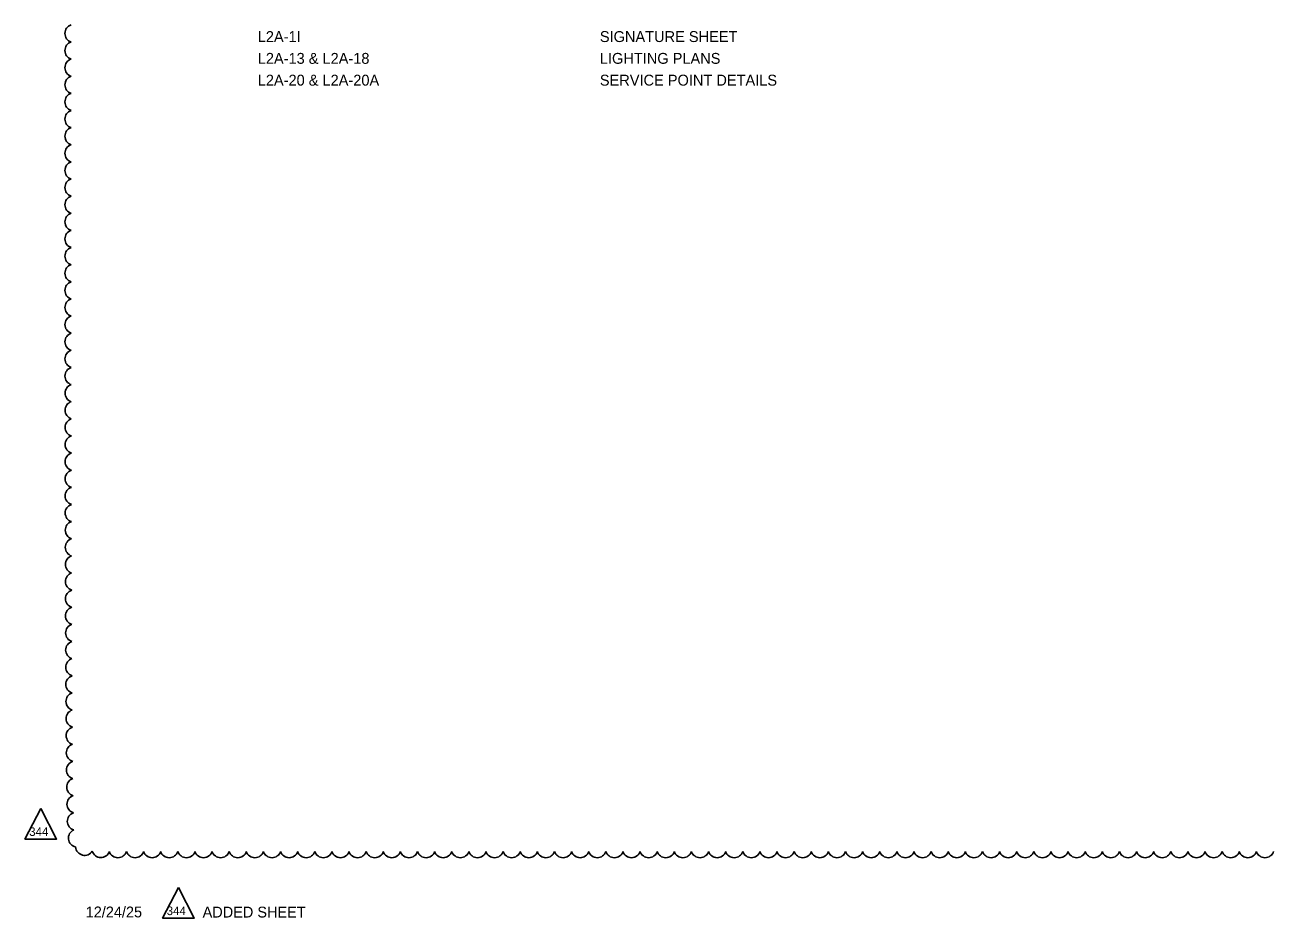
# Model space of a CAD drawing. Extents: x -811 to 10319, y -2309 to 9962.
# Drawn here: x -811.27 to -803.29, y -2308.89 to -2303.15 of the extents above; entities that cross this region are included whole.
import ezdxf

# ---------------------------------------------------------------- set-up
doc = ezdxf.new("R2010")
doc.units = 0
doc.layers.add('ScratchEle_dp', color=7, linetype='Continuous')
doc.layers.add('TextMisc', color=7, linetype='Continuous')

msp = doc.modelspace()

# ---------------------------------------------------------------- linework, layer by layer
at = {"layer": 'ScratchEle_dp'}
for points in [[(-811.1719, -2308.1812), (-811.2741, -2308.3778), (-811.0698, -2308.3778)], [(-810.2869, -2308.6886), (-810.389, -2308.8853), (-810.1848, -2308.8853)]]:
    msp.add_lwpolyline(points, close=True, dxfattribs=at)
for centre, radius, start, end in [((-810.959, -2303.2017), 0.0577, 107.5, 252.5), ((-810.959, -2303.3118), 0.0577, 107.5, 252.5), ((-810.959, -2303.4218), 0.0577, 107.5, 252.5), ((-810.959, -2303.5318), 0.0577, 107.5, 252.5), ((-810.959, -2303.6419), 0.0577, 107.5, 252.5), ((-810.959, -2303.7519), 0.0577, 107.5, 252.5), ((-810.959, -2303.862), 0.0577, 107.5, 252.5), ((-810.959, -2303.972), 0.0577, 107.5, 252.5), ((-810.959, -2304.0821), 0.0577, 107.50009, 252.50009), ((-810.959, -2304.1921), 0.0577, 107.50287, 252.50287), ((-810.959, -2304.3021), 0.0577, 107.50707, 252.50707), ((-810.9589, -2304.4122), 0.0577, 107.51144, 252.51144), ((-810.9589, -2304.5222), 0.0577, 107.51599, 252.51599), ((-810.9589, -2304.6323), 0.0577, 107.52073, 252.52073), ((-810.9588, -2304.7423), 0.0577, 107.52569, 252.52569), ((-810.9588, -2304.8524), 0.0577, 107.53088, 252.53088), ((-810.9587, -2304.9624), 0.0577, 107.53631, 252.53631), ((-810.9586, -2305.0724), 0.0577, 107.54201, 252.54201), ((-810.9585, -2305.1825), 0.0577, 107.548, 252.548), ((-810.9584, -2305.2925), 0.0577, 107.5543, 252.5543), ((-810.9583, -2305.4026), 0.0577, 107.56094, 252.56094), ((-810.9582, -2305.5126), 0.0577, 107.56795, 252.56795), ((-810.9581, -2305.6227), 0.0577, 107.57537, 252.57537), ((-810.9579, -2305.7327), 0.0577, 107.58325, 252.58325), ((-810.9578, -2305.8427), 0.0577, 107.59162, 252.59162), ((-810.9576, -2305.9528), 0.0577, 107.60055, 252.60055), ((-810.9574, -2306.0628), 0.0577, 107.61009, 252.61009), ((-810.9571, -2306.1729), 0.0577, 107.62033, 252.62033), ((-810.9569, -2306.2829), 0.0577, 107.63135, 252.63135), ((-810.9566, -2306.3929), 0.0577, 107.64325, 252.64325), ((-810.9564, -2306.503), 0.0577, 107.65616, 252.65616), ((-810.956, -2306.613), 0.0577, 107.67024, 252.67024), ((-810.9557, -2306.7231), 0.0577, 107.68566, 252.68566), ((-810.9553, -2306.8331), 0.0577, 107.70266, 252.70266), ((-810.9549, -2306.9431), 0.0577, 107.72152, 252.72152), ((-810.9545, -2307.0532), 0.0577, 107.74262, 252.74262), ((-810.954, -2307.1632), 0.0577, 107.76643, 252.76643), ((-810.9534, -2307.2732), 0.0577, 107.79359, 252.79359), ((-810.9529, -2307.3833), 0.0577, 107.82496, 252.82496), ((-810.9522, -2307.4933), 0.0577, 107.86178, 252.86178), ((-810.9515, -2307.6033), 0.0577, 107.9058, 252.9058), ((-810.9506, -2307.7134), 0.0577, 107.95976, 252.95976), ((-810.9497, -2307.8234), 0.0577, 108.02807, 253.02807), ((-810.9486, -2307.9334), 0.0577, 108.11849, 253.11849), ((-810.9473, -2308.0434), 0.0577, 108.24639, 253.24639), ((-810.9456, -2308.1533), 0.0577, 108.44819, 253.44819), ((-810.9434, -2308.2632), 0.0577, 108.8456, 253.8456), ((-810.9363, -2308.3715), 0.0577, 113.71802, 258.71802), ((-810.89, -2308.4245), 0.0576, 183.636, 328.636), ((-810.7854, -2308.4383), 0.0577, 196.27453, 341.27453), ((-810.6758, -2308.4395), 0.0577, 197.5, 342.5), ((-810.5657, -2308.4395), 0.0577, 197.5, 342.5), ((-810.4557, -2308.4395), 0.0577, 197.5, 342.5), ((-810.3457, -2308.4395), 0.0577, 197.5, 342.5), ((-810.2356, -2308.4395), 0.0577, 197.5, 342.5), ((-810.1256, -2308.4395), 0.0577, 197.5, 342.5), ((-810.0155, -2308.4395), 0.0577, 197.5, 342.5), ((-809.9055, -2308.4395), 0.0577, 197.5, 342.5), ((-809.7954, -2308.4395), 0.0577, 197.5, 342.5), ((-809.6854, -2308.4395), 0.0577, 197.5, 342.5), ((-809.5753, -2308.4395), 0.0577, 197.5, 342.5), ((-809.4653, -2308.4395), 0.0577, 197.5, 342.5), ((-809.3553, -2308.4395), 0.0577, 197.5, 342.5), ((-809.2452, -2308.4395), 0.0577, 197.5, 342.5), ((-809.1352, -2308.4395), 0.0577, 197.5, 342.5), ((-809.0251, -2308.4395), 0.0577, 197.5, 342.5), ((-808.9151, -2308.4395), 0.0577, 197.5, 342.5), ((-808.805, -2308.4395), 0.0577, 197.5, 342.5), ((-808.695, -2308.4395), 0.0577, 197.5, 342.5), ((-808.585, -2308.4395), 0.0577, 197.5, 342.5), ((-808.4749, -2308.4395), 0.0577, 197.5, 342.5), ((-808.3649, -2308.4395), 0.0577, 197.5, 342.5), ((-808.2548, -2308.4395), 0.0577, 197.5, 342.5), ((-808.1448, -2308.4395), 0.0577, 197.5, 342.5), ((-808.0347, -2308.4395), 0.0577, 197.5, 342.5), ((-807.9247, -2308.4395), 0.0577, 197.5, 342.5), ((-807.8146, -2308.4395), 0.0577, 197.5, 342.5), ((-807.7046, -2308.4395), 0.0577, 197.5, 342.5), ((-807.5946, -2308.4395), 0.0577, 197.5, 342.5), ((-807.4845, -2308.4395), 0.0577, 197.5, 342.5), ((-807.3745, -2308.4395), 0.0577, 197.5, 342.5), ((-807.2644, -2308.4395), 0.0577, 197.5, 342.5), ((-807.1544, -2308.4395), 0.0577, 197.5, 342.5), ((-807.0443, -2308.4395), 0.0577, 197.5, 342.5), ((-806.9343, -2308.4395), 0.0577, 197.5, 342.5), ((-806.8242, -2308.4395), 0.0577, 197.5, 342.5), ((-806.7142, -2308.4395), 0.0577, 197.5, 342.5), ((-806.6042, -2308.4395), 0.0577, 197.5, 342.5), ((-806.4941, -2308.4395), 0.0577, 197.5, 342.5), ((-806.3841, -2308.4395), 0.0577, 197.5, 342.5), ((-806.274, -2308.4395), 0.0577, 197.5, 342.5), ((-806.164, -2308.4395), 0.0577, 197.5, 342.5), ((-806.0539, -2308.4395), 0.0577, 197.5, 342.5), ((-805.9439, -2308.4395), 0.0577, 197.5, 342.5), ((-805.8339, -2308.4395), 0.0577, 197.5, 342.5), ((-805.7238, -2308.4395), 0.0577, 197.5, 342.5), ((-805.6138, -2308.4395), 0.0577, 197.5, 342.5), ((-805.5037, -2308.4395), 0.0577, 197.5, 342.5), ((-805.3937, -2308.4395), 0.0577, 197.5, 342.5), ((-805.2836, -2308.4395), 0.0577, 197.5, 342.5), ((-805.1736, -2308.4395), 0.0577, 197.5, 342.5), ((-805.0635, -2308.4395), 0.0577, 197.5, 342.5), ((-804.9535, -2308.4395), 0.0577, 197.5, 342.5), ((-804.8435, -2308.4395), 0.0577, 197.5, 342.5), ((-804.7334, -2308.4395), 0.0577, 197.5, 342.5), ((-804.6234, -2308.4395), 0.0577, 197.5, 342.5), ((-804.5133, -2308.4395), 0.0577, 197.5, 342.5), ((-804.4033, -2308.4395), 0.0577, 197.5, 342.5), ((-804.2932, -2308.4395), 0.0577, 197.5, 342.5), ((-804.1832, -2308.4395), 0.0577, 197.5, 342.5), ((-804.0732, -2308.4395), 0.0577, 197.5, 342.5), ((-803.9631, -2308.4395), 0.0577, 197.5, 342.5), ((-803.8531, -2308.4395), 0.0577, 197.5, 342.5), ((-803.743, -2308.4395), 0.0577, 197.5, 342.5), ((-803.633, -2308.4395), 0.0577, 197.5, 342.5), ((-803.5229, -2308.4395), 0.0577, 197.5, 342.5), ((-803.4129, -2308.4395), 0.0577, 197.5, 342.5), ((-803.3028, -2308.4395), 0.0577, 197.5, 342.5)]:
    msp.add_arc(centre, radius, start, end, dxfattribs=at)

# ---------------------------------------------------------------- texts
for s, height, p in [('344', 0.0551, (-811.2462, -2308.3573)), ('12/24/25', 0.0696, (-810.8829, -2308.8805)), ('344', 0.0551, (-810.3623, -2308.8658)), ('ADDED SHEET', 0.0696, (-810.1313, -2308.8812))]:
    msp.add_text(s, height=height, dxfattribs=at).set_placement(p)
at = {"layer": 'TextMisc'}
for s, p in [('L2A-1I', (-809.777, -2303.257)), ('SIGNATURE SHEET', (-807.5781, -2303.257)), ('L2A-13 & L2A-18', (-809.777, -2303.397)), ('LIGHTING PLANS', (-807.5781, -2303.397)), ('L2A-20 & L2A-20A', (-809.777, -2303.537)), ('SERVICE POINT DETAILS', (-807.5781, -2303.537))]:
    msp.add_text(s, height=0.07, dxfattribs=at).set_placement(p)

doc.saveas('drawing.dxf')
